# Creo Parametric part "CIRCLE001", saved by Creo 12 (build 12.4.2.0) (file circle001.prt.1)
Units: Custom; MM, KILOGRAM, SECS

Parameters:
  PTC_WM_ITERATION = "0"
  PTC_WM_VERSION = "-.0"
  PTC_WM_LIFECYCLE_STATE = "In Work"
  PTC_WM_LIFECYCLE = "MO_CADDocument"
  PTC_WM_CREATED_BY = "Maximilian Roepper (Z0017RMS: MO)"
  PTC_WM_CREATED_ON = "18-Sep-26 11:36:42 AM"
  PTC_WM_MODIFIED_BY = "Maximilian Roepper (Z0017RMS: MO)"
  PTC_WM_MODIFIED_ON = "18-Sep-26 11:36:46 AM"
  PDMLINKNUMBER = "PDM000071454831"
  PTC_WM_NAME = "circle001.prt"
  PTC_WM_NUMBER = "PDM000071454831"

Other parameters: WEIGHT, WEIGHT_FACTOR, WEIGHT_ADD, _MASS_TEMP, _DIFF_TEMP, MC_ERRORS, SUPPLIER

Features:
  1. coordinate system
  2. datum plane "PRT_YZ"
  3. datum plane "PRT_XY"
  4. datum plane "PRT_XZ"
  5. coordinate system
  6. datum axis
  7. datum axis
  8. datum axis
  9. coordinate system
  10. imported feature
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
Other named items: PRT, SIEMENS_MO, DRW_VIEW_ORG, PRT_X, PRT_Y, PRT_Z, CS0, ROUGH_GROB

Layers: 00_STD_CSYS-KSYS, 01_STD_PLANES-EBENEN, 02_STD_AXES-ACHSEN, 03_STD_CSYS-KSYS, 24_IMPORT_FEAT-IMPORT_KE

Surfaces: 2 cylinder, 2 plane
